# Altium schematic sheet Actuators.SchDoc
size A; DocumentNumber: 5; SheetNumber: 5; SheetTotal: 5
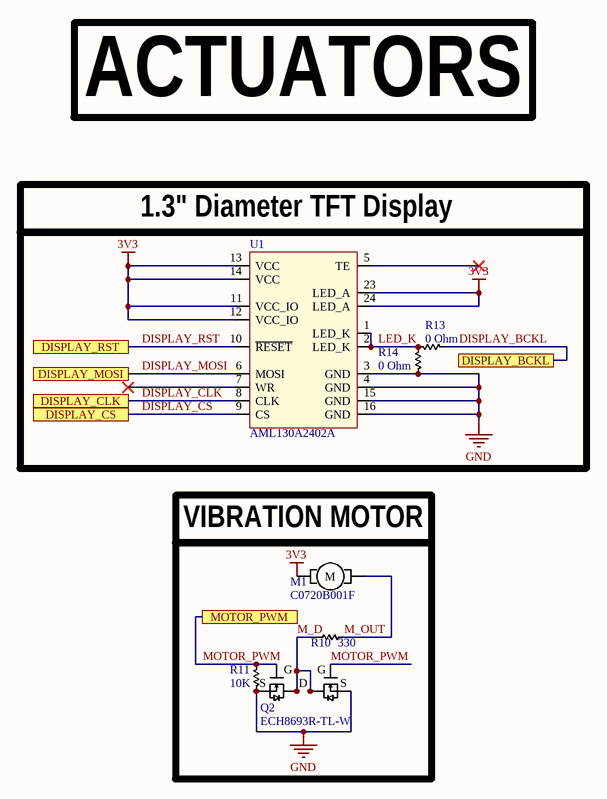
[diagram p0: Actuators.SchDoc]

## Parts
M1  C0720B001F  [C0720B001F]
Q2  ECH8693R-TL-W  [ECH8693R-TL-W]
R10  330  [RES_0603_HIGH]
R11  10K  [RES_0603_HIGH]
R13  0 Ohm  [RES_0603_HIGH]
R14  0 Ohm  [RES_0603_HIGH]  (no BOM)
U1  AML130A2402A  [AML130A2402A]

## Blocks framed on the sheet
1.3" Diameter TFT Display: R13 R14 U1
VIBRATION MOTOR: M1 Q2 R10 R11

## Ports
DISPLAY_BCKL, DISPLAY_CLK, DISPLAY_CS, DISPLAY_MOSI, DISPLAY_RST, MOTOR_PWM

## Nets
3V3: M1.1 U1.11(VCC_IO) U1.12(VCC_IO) U1.13(VCC) U1.14(VCC) U1.23(LED_A) U1.24(LED_A)
GND: Q2.1(S1) Q2.3(S2) R11.1 R14.2 U1.3(GND) U1.4(GND) U1.15(GND) U1.16(GND)
DISPLAY_BCKL: R13.1 ; port DISPLAY_BCKL
DISPLAY_CLK: U1.8(CLK) ; port DISPLAY_CLK
DISPLAY_CS: U1.9(CS) ; port DISPLAY_CS
DISPLAY_MOSI: U1.6(MOSI) ; port DISPLAY_MOSI
DISPLAY_RST: U1.10(~{RESET}) ; port DISPLAY_RST
LED_K: R13.2 R14.1 U1.1(LED_K) U1.2(LED_K)
M_D: Q2.5(D) Q2.6(D) Q2.7(D) Q2.8(D) R10.1
M_OUT: M1.2 R10.2
MOTOR_PWM: Q2.2(G1) Q2.4(G2) R11.2 ; port MOTOR_PWM

Not connected (* = marked no-connect by the designer): U1 5(TE)* 7(WR)*

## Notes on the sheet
- ACTUATORS

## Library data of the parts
M1 = C0720B001F: DC Motor Vibration, ERM 10000 RPM 3VDC
Q2 = ECH8693R-TL-W: Mosfet Array 2 N-Channel (Dual) Common Drain 24V 14A 1.4W Surface Mount SOT-28FL/ECH8
R10 R11 R13 R14 = Resistor_0603: 0603 Resistor
U1 = AML130A2402A: AML130A2402A Round 1.3" TFT Display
